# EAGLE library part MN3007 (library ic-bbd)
1024-Stage Lo Noise BBD
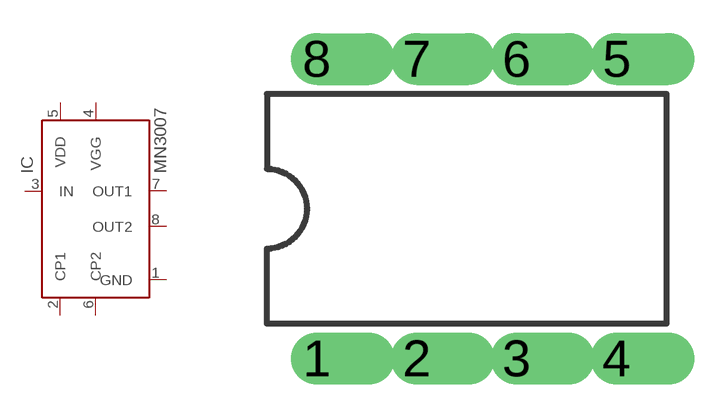
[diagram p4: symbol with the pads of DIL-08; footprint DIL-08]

Designator prefix IC

## MN3007  [DIL-08]
1  GND
2  CP1
3  IN
4  VGG
5  VDD
6  CP2
7  OUT1
8  OUT2

## Footprint DIL-08 (pad centres in mm)
Dual In Line Package
drill 0.813 offset: 1 -3.81,-3.81; 2 -1.27,-3.81; 3 1.27,-3.81; 4 3.81,-3.81; 5 3.81,3.81; 6 1.27,3.81; 7 -1.27,3.81; 8 -3.81,3.81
